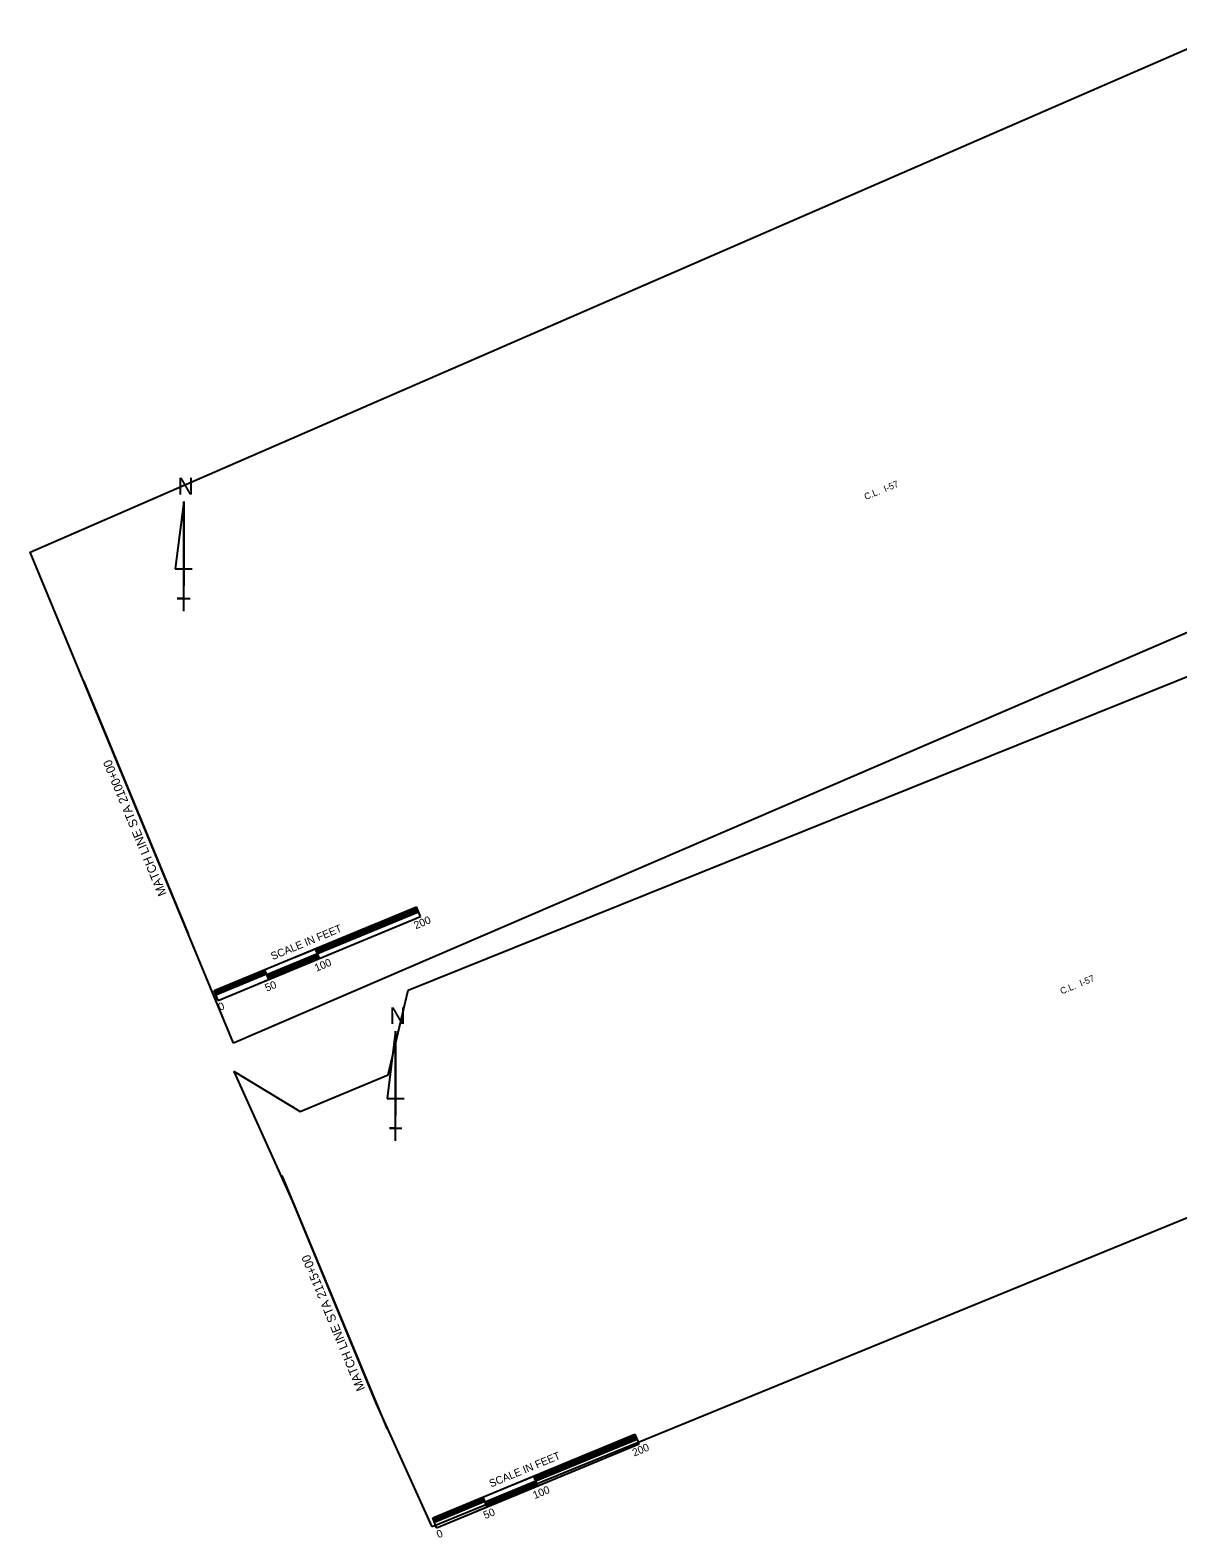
# Model space of a CAD drawing. Extents: x 1716142 to 1718238, y 765201 to 766730.
# Drawn here: x 1716142 to 1717190, y 765201 to 766578 of the extents above; entities that cross this region are included whole.
import ezdxf

# ---------------------------------------------------------------- set-up
doc = ezdxf.new("R2010")
doc.units = 0
for name, color, linetype in [('R_6IN_DASHED-RPM_WHITE_ENHANCED THERMO', 7, 'Continuous'), ('R_6IN_DBL_YELLOW_REFLECTORIZED_PAINT', 7, 'Continuous'), ('R_PM_DOTTED_LINE', 7, 'Continuous'), ('R_RPM_TYPE 2_RED-WHITE', 7, 'Continuous'), ('R_WORDS_WHITE_THERMO', 7, 'Continuous')]:
    doc.layers.add(name, color=color, linetype=linetype)

msp = doc.modelspace()

# ---------------------------------------------------------------- linework, layer by layer
at = {"layer": 'R_6IN_DBL_YELLOW_REFLECTORIZED_PAINT'}
for p, q in [((1716190.2, 765983.7), (1716285.8, 765752.7)), ((1716371.4, 765531.8), (1716467.1, 765300.8))]:
    msp.add_line(p, q, dxfattribs=at)
at = {"layer": 'R_PM_DOTTED_LINE'}
for p, q in [((1716281.7, 766147.3), (1716274, 766085.8)), ((1716281.7, 766047.3), (1716281.7, 766147.3)), ((1716281.7, 766147.3), (1716281.7, 766070.4)), ((1716274, 766085.8), (1716289.4, 766085.8)), ((1716281.7, 766047.3), (1716281.7, 766070.4)), ((1716281.7, 766058.8), (1716275.9, 766058.8)), ((1716275.9, 766058.8), (1716287.5, 766058.8)), ((1716281.7, 766047.3), (1716281.7, 766058.8)), ((1716475.2, 765663.7), (1716467.5, 765602.1)), ((1716475.2, 765563.7), (1716475.2, 765663.7)), ((1716475.2, 765663.7), (1716475.2, 765586.8)), ((1716467.5, 765602.1), (1716482.9, 765602.1)), ((1716475.2, 765563.7), (1716475.2, 765586.8)), ((1716475.2, 765575.2), (1716469.5, 765575.2)), ((1716469.5, 765575.2), (1716481, 765575.2)), ((1716475.2, 765563.7), (1716475.2, 765575.2))]:
    msp.add_line(p, q, dxfattribs=at)
at = {"layer": 'R_RPM_TYPE 2_RED-WHITE'}
for points in [[(1716327.3, 765652.6), (1716141.5, 766101.2), (1717237.3, 766577.7), (1717309.6, 766566), (1717434.3, 766536.2), (1717499.4, 766534.7), (1717585.6, 766534.6), (1717662.1, 766349.8), (1717667.2, 766337.9), (1717590.3, 766278.6), (1717437.4, 766130.6)], [(1716508.6, 765211), (1716457.5, 765323.9), (1716381, 765508.7), (1716327.7, 765626.8), (1716388.1, 765590.2), (1716468.3, 765623.9), (1716486.6, 765701.2), (1717720.1, 766197.7), (1717766.8, 766082.7), (1717843.3, 765897.9), (1717903.1, 765781.4)]]:
    msp.add_lwpolyline(points, close=True, dxfattribs=at)
at = {"layer": 'R_WORDS_WHITE_THERMO'}
for p, q in [((1716383.5, 765731.3), (1716494.4, 765777.2)), ((1716402.3, 765738.2), (1716494.7, 765776.5)), ((1716498.1, 765768.3), (1716494.4, 765777.2)), ((1716313.3, 765691.8), (1716498.1, 765768.4)), ((1716402.6, 765737.5), (1716495, 765775.8)), ((1716402.9, 765736.7), (1716495.3, 765775)), ((1716403.2, 765736), (1716495.6, 765774.3)), ((1716403.5, 765735.3), (1716495.9, 765773.5)), ((1716403.9, 765734.5), (1716496.2, 765772.8)), ((1716309.6, 765700.7), (1716457.4, 765761.9)), ((1716403.9, 765734.5), (1716459.3, 765757.5)), ((1716405.7, 765730.1), (1716402, 765738.9)), ((1716350.3, 765707.1), (1716387.2, 765722.4)), ((1716357.7, 765715.4), (1716403.9, 765734.5)), ((1716358, 765714.6), (1716404.2, 765733.8)), ((1716358.3, 765713.9), (1716404.5, 765733)), ((1716358.6, 765713.2), (1716404.8, 765732.3)), ((1716358.9, 765712.4), (1716405.1, 765731.6)), ((1716359.2, 765711.7), (1716405.4, 765730.8)), ((1716309.6, 765700.7), (1716346.6, 765716)), ((1716309.9, 765700), (1716356.1, 765719.1)), ((1716310.2, 765699.2), (1716356.4, 765718.3)), ((1716310.5, 765698.5), (1716356.7, 765717.6)), ((1716310.8, 765697.7), (1716357, 765716.9)), ((1716311.2, 765697), (1716357.3, 765716.1)), ((1716359.5, 765711), (1716355.8, 765719.8)), ((1716313.3, 765691.8), (1716309.6, 765700.7)), ((1716583, 765249.8), (1716693.8, 765295.7)), ((1716601.8, 765256.7), (1716694.1, 765295)), ((1716697.5, 765286.8), (1716693.9, 765295.7)), ((1716512.7, 765210.3), (1716697.5, 765286.9)), ((1716602.1, 765256), (1716694.5, 765294.3)), ((1716602.4, 765255.3), (1716694.8, 765293.5)), ((1716602.7, 765254.5), (1716695.1, 765292.8)), ((1716603, 765253.8), (1716695.4, 765292)), ((1716603.3, 765253), (1716695.7, 765291.3)), ((1716509.1, 765219.2), (1716656.9, 765280.4)), ((1716603.3, 765253), (1716658.7, 765276)), ((1716557.1, 765233.9), (1716603.3, 765253)), ((1716605.1, 765248.6), (1716601.5, 765257.5)), ((1716549.7, 765225.6), (1716586.7, 765240.9)), ((1716557.4, 765233.2), (1716603.6, 765252.3)), ((1716557.7, 765232.4), (1716603.9, 765251.6)), ((1716558, 765231.7), (1716604.2, 765250.8)), ((1716558.3, 765230.9), (1716604.5, 765250.1)), ((1716558.6, 765230.2), (1716604.8, 765249.3)), ((1716509.1, 765219.2), (1716546, 765234.5)), ((1716509.4, 765218.5), (1716555.6, 765237.6)), ((1716509.7, 765217.7), (1716555.9, 765236.9)), ((1716510, 765217), (1716556.2, 765236.1)), ((1716510.3, 765216.2), (1716556.5, 765235.4)), ((1716510.6, 765215.5), (1716556.8, 765234.6)), ((1716558.9, 765229.5), (1716555.3, 765238.3)), ((1716512.7, 765210.3), (1716509.1, 765219.2))]:
    msp.add_line(p, q, dxfattribs=at)

# ---------------------------------------------------------------- texts
at = {"layer": 'R_6IN_DASHED-RPM_WHITE_ENHANCED THERMO'}
for p in [(1716904.6, 766148.6), (1717083.5, 765697.2)]:
    msp.add_text('C.L.  I-57', height=6, rotation=22.3523, dxfattribs=at).set_placement(p)
at = {"layer": 'R_6IN_DBL_YELLOW_REFLECTORIZED_PAINT'}
for s, p in [('MATCH LINE STA 2100+00', (1716266.3, 765789)), ('MATCH LINE STA 2115+00', (1716447.5, 765337.1))]:
    msp.add_text(s, height=8, rotation=112.5, dxfattribs=at).set_placement(p)
at = {"layer": 'R_PM_DOTTED_LINE'}
for p in [(1716276.1, 766153.7), (1716469.6, 765670.1)]:
    msp.add_text('N', height=15.4, rotation=360, dxfattribs=at).set_placement(p)
at = {"layer": 'R_WORDS_WHITE_THERMO'}
for s, height, p in [('200', 7, (1716493.7, 765756.7)), ('SCALE IN FEET', 7.001, (1716363, 765728.5)), ('100', 7, (1716402.9, 765717.9)), ('50', 7, (1716357.6, 765699.6)), ('0', 7, (1716314.9, 765682.1)), ('200', 7, (1716693.1, 765275.2)), ('SCALE IN FEET', 7.001, (1716562.4, 765247)), ('100', 7, (1716602.3, 765236.4)), ('50', 7, (1716557.1, 765218.1)), ('0', 7, (1716514.3, 765200.6))]:
    msp.add_text(s, height=height, rotation=22.5003, dxfattribs=at).set_placement(p)

doc.saveas('drawing.dxf')
